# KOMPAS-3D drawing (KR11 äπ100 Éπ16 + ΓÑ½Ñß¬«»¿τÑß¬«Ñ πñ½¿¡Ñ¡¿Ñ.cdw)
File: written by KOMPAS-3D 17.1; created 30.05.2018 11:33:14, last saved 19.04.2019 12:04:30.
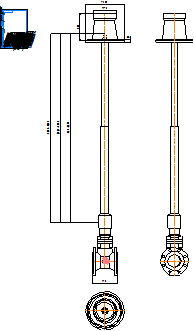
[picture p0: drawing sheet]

Sheet 1: A4, portrait

Title block, sheet 1: name: KR11 Ду100 Ру16 + / телескопическое удлинение; material: Внимание! Данный продукт является объектом авторского права ООО «Торговый Дом АДЛ». / Запрещается изменение, копирование, распространение / (в том числе путем копирования на другие сайты и ресурсы в Интернете) / или любое иное использование информации и объектов без предварительного / согласия правообладателя (ООО «Торговый Дом АДЛ»).; mass: 55,6; sheets: 1; organisation: ООО "Торговый дом АДЛ"; sheet format: A4; stored path: \\adlc.lan\data\АДЛ_ПКД\3D-модели\ADL production\Клиновые задвижки серии KR ГРАНАР\Клиновые задвижки KR11 с телескопическим удлинением\KOMPAS 2D\KR11 Ду100 Ру16 + телескопическое удлинение.cdw

Views: Вид 1, Проекционный вид 2, Проекционный вид 3
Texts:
  kka
  adl
Dimensions and other numbers on the sheet: 190; 846-; 1465; 1547-2865; 2160-3160; 300; 18; 210; 175; 1:1; 1; 55,6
